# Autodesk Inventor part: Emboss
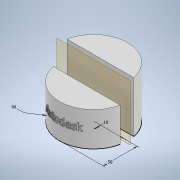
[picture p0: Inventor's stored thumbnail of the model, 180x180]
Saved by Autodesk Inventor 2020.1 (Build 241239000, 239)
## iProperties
Created: 2019-10
Part Number: Emboss
Material: Generic
Document SubType Name: Modeling
Designer: Synergysoft Dell02
Density: 1 g/cm^3
Appearance: Default
Author: Synergysoft Dell02
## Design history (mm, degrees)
sketch "Sketch1"
  geometry: L1 (50, 0)-(-50, 0); L2 (48.99, 10)-(-48.99, 10); L3 (0, 0)-(0, 50); L4 (48.99, -10)-(-48.99, -10); A1 r 50 centre (0, 0) between (48.99, 10) and (-48.99, 10); A2 r 50 centre (0, 0) between (-48.99, -10) and (48.99, -10); 1 further point
  constraints: 8 end point, 5 point on circle, 2 centre point, 2 horizontal, 2 midpoint, 2 symmetric about line, 1 coincident, 1 vertical, 1 other
  dimensions: "d7" = 10 distance from line of point (0, 0) L2; "d8" = 50 distance of L3.start L3.end; "d9" = 50 radius of A1
extrude "Extrusion1" new body sketch "Sketch1" distance "d1" = 50; taper "d2" = 0 deg
sketch "Sketch6"
  geometry: L1 (-35.107, 37.046)-(35.107, 37.046); L2 (35.107, 37.046)-(35.107, 15.711); L3 (35.107, 15.711)-(-35.107, 15.711); L4 (-35.107, 15.711)-(-35.107, 37.046); 2 further points
  constraints: 1 midpoint, 1 vertical alignment, 2 other
emboss "Emboss5" sketch "Sketch6" dims "d24" = 1, "d25" = 2 deg
extrude "Extrusion3" join sketch "Sketch1" distance "d26" = 75; taper "d27" = 0 deg
workplane "Work Plane1"
sketch "Sketch2"
  geometry: L1 (-25, 40)-(25, 40); L2 (25, 40)-(25, 10); L3 (25, 10)-(-25, 10); L4 (-25, 10)-(-25, 40); L5 (50, 0)-(-50, 0) reference; L6 (50, 0)-(50, 50) reference; 7 further points
  constraints: 4 midpoint, 1 horizontal alignment, 1 vertical alignment, 2 other
  dimensions: "d3" = 50 distance of L2.end L3.end; "d4" = 30 distance of L3.end L1.start
emboss "Emboss1" sketch "Sketch2" dims "d5" = 5, "d6" = 0
extrude "Extrusion2" join sketch "Sketch1" distance "d10" = 75; taper "d11" = 0 deg
workplane "Work Plane2"
sketch "Sketch3"
  geometry: L1 (-25, 52.5)-(25, 52.5); L2 (25, 52.5)-(25, 22.5); L3 (25, 22.5)-(-25, 22.5); L4 (-25, 22.5)-(-25, 52.5); L5 (48.99, 0)-(-48.99, 0) reference; L6 (-48.99, 0)-(-48.99, 75) reference; 5 further points
  constraints: 4 midpoint, 1 horizontal alignment, 1 vertical alignment, 2 other
  dimensions: "d12" = 50 distance of L1.start L1.end; "d13" = 30 distance of L3.end L1.start
emboss "Emboss2" sketch "Sketch3" dims "d14" = 5, "d15" = 0
sketch "Sketch4"
  geometry: L1 (-34.765, -12.948)-(33.701, -12.948); L2 (33.701, -12.948)-(33.701, -37.426); L3 (33.701, -37.426)-(-34.765, -37.426); L4 (-34.765, -37.426)-(-34.765, -12.948); 1 further point
  constraints: 2 other
emboss "Emboss3" sketch "Sketch4" dims "d16" = 2, "d17" = 0
loft "Loft1" dims "d18" = 0, "d19" = 90 deg, "d20" = 0, "d21" = 90 deg
  node "Edges1"
  node "Edges2"
sketch "Sketch5"
  geometry: L1 (8.943, 23.684)-(89.036, 23.684); L2 (89.036, 23.684)-(89.036, 9.328); L3 (89.036, 9.328)-(8.943, 9.328); L4 (8.943, 9.328)-(8.943, 23.684); 1 further point
  constraints: 2 other
emboss "Emboss4" sketch "Sketch5" dims "d22" = 1, "d23" = 2 deg
body "Solid1"
